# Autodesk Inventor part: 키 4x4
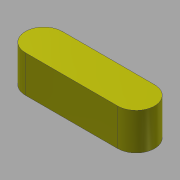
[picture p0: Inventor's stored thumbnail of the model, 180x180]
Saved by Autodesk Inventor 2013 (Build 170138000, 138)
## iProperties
Created: 2016-04
Part Number: 키 4x4
Document SubType Name: Modeling
Designer: mdu
Density: 1 g/cm^3
Mass: 0.210265 g
Surface Area: 2.35398 cm^2
Volume: 0.210265 cm^3
Material: 강철, 연강
Author: mdu
Revision Number: 1
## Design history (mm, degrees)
sketch "스케치1"
  geometry: L1 (-5, -2)-(5, -2); L2 (5, 2)-(-5, 2); A1 r 2 centre (5, 0) between (5, -2) and (5, 2); A2 r 2 centre (-5, 0) between (-5, 2) and (-5, -2); 2 further points
  constraints: 4 end point, 4 point on circle, 4 tangent, 2 centre point, 1 horizontal, 1 horizontal alignment, 1 midpoint, 1 parallel, 1 vertical alignment
  dimensions: "d0" = 4 distance between parallel lines of L1 L2; "d1" = 14 dimension on A1 A2
extrude "돌출1" new body sketch "스케치1" stored distance "d2" = 4; taper "d3" = 0 deg
node "솔리드1"
